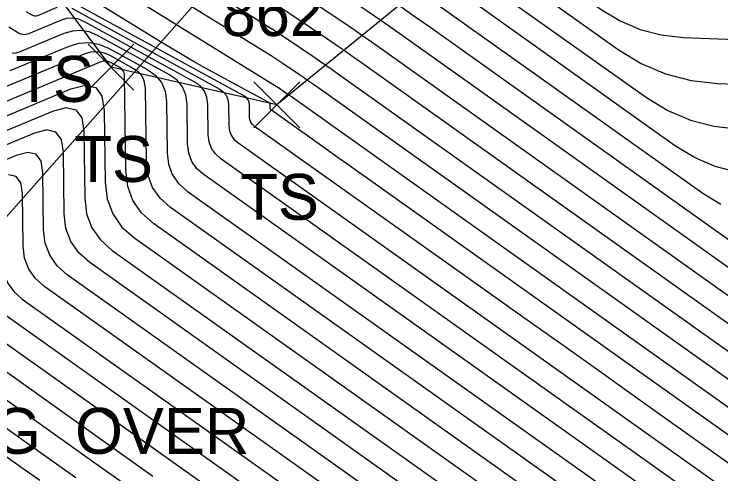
# Model space of a CAD drawing. Extents: x 1650836 to 1652450, y 332578 to 333908.
# Drawn here: x 1652155.83 to 1652186.58, y 332802.49 to 332822.5 of the extents above; entities that cross this region are included whole.
import ezdxf

# ---------------------------------------------------------------- set-up
doc = ezdxf.new("R2010")
doc.units = 0
for name, color, linetype in [('DCP', 7, 'Continuous'), ('L_A', 7, 'Continuous'), ('L_I', 7, 'Continuous'), ('L_TIC', 7, 'Continuous'), ('LELB', 7, 'Continuous'), ('LSOGCMA', 7, 'Continuous'), ('LSOGCMI', 7, 'Continuous'), ('M_C', 7, 'Continuous')]:
    doc.layers.add(name, color=color, linetype=linetype)

msp = doc.modelspace()

# ---------------------------------------------------------------- linework, layer by layer
at = {"layer": 'DCP'}
msp.add_lwpolyline([(1652097.436, 332748.039), (1652173.064, 332833.561)], dxfattribs=at)
at = {"layer": 'L_TIC'}
for points in [[(1652159.046, 332819.196), (1652161.046, 332821.196)], [(1652161.046, 332819.196), (1652159.046, 332821.196)], [(1652166.264, 332817.548), (1652168.264, 332819.548)], [(1652168.264, 332817.548), (1652166.264, 332819.548)]]:
    msp.add_lwpolyline(points, dxfattribs=at)
at = {"layer": 'LELB'}
msp.add_lwpolyline([(1652179.275, 332828.339), (1652167.264, 332818.548), (1652160.046, 332820.196), (1652157.477, 332823.68), (1652166.593, 332836.388)], dxfattribs=at)
at = {"layer": 'LSOGCMA'}
for points in [[(1652146.793, 332842.65), (1652157.507, 332833.342), (1652157.974, 332832.878), (1652158.365, 332832.365), (1652158.679, 332831.801), (1652158.916, 332831.187), (1652159.714, 332828.632), (1652159.96, 332828.029), (1652160.298, 332827.497), (1652160.728, 332827.037), (1652161.251, 332826.649), (1652166.303, 332823.515), (1652166.698, 332823.267), (1652167.091, 332823.015), (1652167.482, 332822.76), (1652167.869, 332822.501), (1652169.416, 332821.455), (1652169.802, 332821.193), (1652170.186, 332820.928), (1652170.569, 332820.661), (1652170.95, 332820.392), (1652190.692, 332806.342)], [(1652189.751, 332794.813), (1652162.63, 332814.09), (1652162.18, 332814.488), (1652161.856, 332814.952), (1652161.658, 332815.482), (1652161.587, 332816.079), (1652161.544, 332819.263), (1652161.509, 332819.54), (1652161.409, 332819.779), (1652161.245, 332819.979), (1652161.017, 332820.141), (1652159.977, 332820.71), (1652159.715, 332820.82), (1652159.45, 332820.866), (1652159.182, 332820.848), (1652158.91, 332820.766), (1652155.252, 332819.242)], [(1652161.871, 332802.38), (1652153.245, 332808.511), (1652152.988, 332808.739), (1652152.802, 332809.004), (1652152.689, 332809.307), (1652152.649, 332809.648), (1652152.629, 332811.087), (1652152.584, 332811.385), (1652152.456, 332811.558), (1652152.247, 332811.606), (1652151.956, 332811.53), (1652150.547, 332810.943), (1652150.205, 332810.841), (1652149.869, 332810.824), (1652149.539, 332810.891), (1652149.216, 332811.043), (1652146.021, 332812.978), (1652145.391, 332813.378), (1652144.847, 332813.757)]]:
    msp.add_lwpolyline(points, dxfattribs=at)
at = {"layer": 'LSOGCMI'}
for points in [[(1652160.714, 332847.161), (1652164.675, 332834.475), (1652164.777, 332834.225), (1652164.918, 332834.004), (1652165.096, 332833.813), (1652165.313, 332833.652), (1652166.257, 332833.066), (1652166.492, 332832.919), (1652166.726, 332832.769), (1652166.959, 332832.617), (1652167.19, 332832.463), (1652174.934, 332827.23), (1652175.747, 332826.677), (1652176.557, 332826.119), (1652177.363, 332825.556), (1652178.166, 332824.989), (1652181.371, 332822.708), (1652182.195, 332822.204), (1652183.064, 332821.833), (1652183.979, 332821.594), (1652184.939, 332821.488), (1652190.629, 332821.259)], [(1652186.578, 332814.214), (1652185.792, 332814.695), (1652174.966, 332822.4), (1652174.169, 332822.963), (1652173.37, 332823.521), (1652172.567, 332824.074), (1652171.761, 332824.623), (1652167.994, 332827.168), (1652167.452, 332827.53), (1652166.906, 332827.888), (1652166.356, 332828.24), (1652165.804, 332828.586), (1652163.586, 332829.962), (1652163.076, 332830.341), (1652162.657, 332830.789), (1652162.328, 332831.307), (1652162.088, 332831.895), (1652160.207, 332837.92), (1652159.756, 332839.084), (1652159.161, 332840.153), (1652158.42, 332841.128), (1652157.534, 332842.008), (1652153.435, 332845.569)], [(1652187.017, 332812.607), (1652173.962, 332821.898), (1652173.269, 332822.388), (1652172.574, 332822.873), (1652171.876, 332823.354), (1652171.175, 332823.831), (1652168.195, 332825.844), (1652167.575, 332826.259), (1652166.951, 332826.667), (1652166.322, 332827.07), (1652165.69, 332827.466), (1652163.154, 332829.039), (1652162.572, 332829.472), (1652162.092, 332829.985), (1652161.715, 332830.578), (1652161.441, 332831.25), (1652159.885, 332836.236), (1652159.487, 332837.263), (1652158.962, 332838.206), (1652158.308, 332839.066), (1652157.527, 332839.841), (1652151.774, 332844.84)], [(1652188.242, 332810.519), (1652172.958, 332821.396), (1652172.369, 332821.812), (1652171.778, 332822.225), (1652171.185, 332822.634), (1652170.588, 332823.039), (1652168.199, 332824.654), (1652167.6, 332825.054), (1652166.997, 332825.449), (1652166.39, 332825.838), (1652165.779, 332826.221), (1652162.722, 332828.117), (1652162.067, 332828.604), (1652161.527, 332829.181), (1652161.103, 332829.848), (1652160.795, 332830.605), (1652159.562, 332834.553), (1652159.218, 332835.442), (1652158.763, 332836.259), (1652158.197, 332837.003), (1652157.521, 332837.675), (1652150.114, 332844.11)], [(1652137.973, 332843.797), (1652157.487, 332826.843), (1652157.64, 332826.691), (1652157.768, 332826.523), (1652157.871, 332826.339), (1652157.948, 332826.138), (1652158.21, 332825.301), (1652158.29, 332825.104), (1652158.401, 332824.93), (1652158.542, 332824.779), (1652158.713, 332824.652), (1652167.089, 332819.457), (1652167.161, 332819.411), (1652167.233, 332819.365), (1652167.304, 332819.319), (1652167.375, 332819.271), (1652167.658, 332819.08), (1652167.729, 332819.032), (1652167.799, 332818.983), (1652167.869, 332818.935), (1652167.939, 332818.885), (1652194.367, 332800.077)], [(1652148.454, 332843.38), (1652157.514, 332835.509), (1652158.086, 332834.941), (1652158.564, 332834.312), (1652158.948, 332833.622), (1652159.239, 332832.87), (1652160.216, 332829.742), (1652160.516, 332829.004), (1652160.93, 332828.353), (1652161.457, 332827.79), (1652162.097, 332827.314), (1652166.041, 332824.868), (1652166.544, 332824.553), (1652167.044, 332824.232), (1652167.541, 332823.907), (1652168.034, 332823.577), (1652170.002, 332822.247), (1652170.493, 332821.913), (1652170.982, 332821.576), (1652171.469, 332821.237), (1652171.954, 332820.894), (1652189.467, 332808.43)], [(1652141.221, 332843.147), (1652157.494, 332829.01), (1652157.751, 332828.754), (1652157.967, 332828.47), (1652158.14, 332828.159), (1652158.271, 332827.821), (1652158.711, 332826.411), (1652158.847, 332826.079), (1652159.033, 332825.785), (1652159.27, 332825.532), (1652159.559, 332825.317), (1652166.827, 332820.809), (1652167.007, 332820.697), (1652167.186, 332820.582), (1652167.363, 332820.466), (1652167.54, 332820.348), (1652168.244, 332819.872), (1652168.42, 332819.752), (1652168.595, 332819.632), (1652168.769, 332819.51), (1652168.943, 332819.387), (1652193.142, 332802.166)], [(1652144.469, 332842.497), (1652157.5, 332831.176), (1652157.863, 332830.816), (1652158.166, 332830.417), (1652158.409, 332829.98), (1652158.594, 332829.504), (1652159.213, 332827.522), (1652159.403, 332827.054), (1652159.665, 332826.641), (1652159.999, 332826.284), (1652160.405, 332825.983), (1652166.565, 332822.162), (1652166.852, 332821.982), (1652167.138, 332821.799), (1652167.422, 332821.613), (1652167.705, 332821.424), (1652168.83, 332820.664), (1652169.111, 332820.473), (1652169.391, 332820.28), (1652169.669, 332820.086), (1652169.946, 332819.89), (1652191.917, 332804.254)], [(1652195.592, 332797.989), (1652171.198, 332815.35), (1652170.775, 332815.65), (1652170.352, 332815.951), (1652169.93, 332816.251), (1652169.507, 332816.552), (1652167.024, 332818.317), (1652167.001, 332818.337), (1652166.984, 332818.361), (1652166.974, 332818.389), (1652166.97, 332818.42), (1652166.968, 332818.551), (1652166.964, 332818.581), (1652166.953, 332818.607), (1652166.935, 332818.629), (1652166.91, 332818.647), (1652164.134, 332820.167), (1652163.664, 332820.429), (1652163.197, 332820.697), (1652162.734, 332820.971), (1652162.275, 332821.252), (1652157.867, 332823.986)], [(1652177.84, 332824.004), (1652182.117, 332820.96), (1652183.116, 332820.349), (1652184.17, 332819.899), (1652185.279, 332819.61), (1652186.443, 332819.481), (1652191.209, 332819.289)], [(1652196.817, 332795.901), (1652183.175, 332805.609), (1652181.466, 332806.825), (1652179.756, 332808.041), (1652178.047, 332809.257), (1652176.337, 332810.473), (1652166.292, 332817.612), (1652166.197, 332817.696), (1652166.129, 332817.793), (1652166.088, 332817.905), (1652166.073, 332818.03), (1652166.066, 332818.558), (1652166.05, 332818.682), (1652166.005, 332818.788), (1652165.932, 332818.877), (1652165.83, 332818.95), (1652157.779, 332823.359)], [(1652176.973, 332823.404), (1652183.342, 332818.872), (1652184.27, 332818.304), (1652185.25, 332817.886), (1652186.28, 332817.617), (1652187.361, 332817.498)], [(1652156.342, 332822.619), (1652156.595, 332822.466), (1652156.659, 332822.436), (1652156.725, 332822.423), (1652156.791, 332822.426), (1652156.859, 332822.446), (1652157.701, 332822.797)], [(1652158.338, 332822.764), (1652164.751, 332819.252), (1652164.929, 332819.125), (1652165.057, 332818.969), (1652165.135, 332818.783), (1652165.163, 332818.566), (1652165.176, 332817.64), (1652165.202, 332817.42), (1652165.275, 332817.225), (1652165.394, 332817.054), (1652165.559, 332816.908), (1652186.902, 332801.738)], [(1652187.28, 332815.625), (1652186.329, 332815.873), (1652185.424, 332816.259), (1652184.567, 332816.783), (1652175.969, 332822.902)], [(1652193.912, 332795.53), (1652164.827, 332816.204), (1652164.59, 332816.413), (1652164.42, 332816.657), (1652164.316, 332816.936), (1652164.278, 332817.249), (1652164.261, 332818.574), (1652164.221, 332818.883), (1652164.109, 332819.15), (1652163.926, 332819.373), (1652163.671, 332819.554), (1652158.896, 332822.169), (1652158.639, 332822.277), (1652158.378, 332822.323), (1652158.114, 332822.305), (1652157.847, 332822.224), (1652156.457, 332821.645), (1652156.345, 332821.612), (1652156.236, 332821.606), (1652156.128, 332821.628), (1652156.023, 332821.678), (1652155.605, 332821.931)], [(1652193.359, 332794.698), (1652164.095, 332815.499), (1652163.787, 332815.771), (1652163.565, 332816.089), (1652163.43, 332816.451), (1652163.381, 332816.859), (1652163.358, 332818.581), (1652163.306, 332818.984), (1652163.161, 332819.331), (1652162.923, 332819.621), (1652162.591, 332819.856), (1652159.455, 332821.574), (1652159.097, 332821.725), (1652158.733, 332821.788), (1652158.365, 332821.764), (1652157.992, 332821.651), (1652156.056, 332820.844), (1652155.9, 332820.798), (1652155.747, 332820.79)], [(1652155.654, 332820.043), (1652158.221, 332821.113), (1652158.657, 332821.244), (1652159.089, 332821.273), (1652159.515, 332821.199), (1652159.935, 332821.022), (1652161.606, 332820.107), (1652161.973, 332819.847), (1652162.236, 332819.525), (1652162.397, 332819.142), (1652162.454, 332818.697), (1652162.484, 332816.469), (1652162.544, 332815.967), (1652162.711, 332815.52), (1652162.983, 332815.13), (1652163.362, 332814.795), (1652192.807, 332793.866)], [(1652186.45, 332795.935), (1652161.897, 332813.386), (1652161.376, 332813.847), (1652161.001, 332814.384), (1652160.772, 332814.998), (1652160.69, 332815.689), (1652160.635, 332819.83), (1652160.62, 332819.939), (1652160.581, 332820.032), (1652160.517, 332820.111), (1652160.427, 332820.174), (1652160.019, 332820.398), (1652159.916, 332820.441), (1652159.812, 332820.46), (1652159.707, 332820.452), (1652159.6, 332820.42), (1652154.851, 332818.44)], [(1652154.449, 332817.639), (1652158.301, 332819.245), (1652158.929, 332819.409), (1652159.38, 332819.305), (1652159.654, 332818.933), (1652159.753, 332818.292), (1652159.794, 332815.192), (1652159.882, 332814.457), (1652160.125, 332813.804), (1652160.524, 332813.233), (1652161.078, 332812.743), (1652183.149, 332797.056)], [(1652154.047, 332816.838), (1652157.508, 332818.281), (1652158.093, 332818.434), (1652158.514, 332818.337), (1652158.77, 332817.989), (1652158.862, 332817.391), (1652158.901, 332814.499), (1652158.983, 332813.813), (1652159.21, 332813.204), (1652159.582, 332812.671), (1652160.099, 332812.214), (1652179.848, 332798.177)], [(1652176.547, 332799.299), (1652159.12, 332811.685), (1652158.64, 332812.11), (1652158.295, 332812.604), (1652158.084, 332813.17), (1652158.008, 332813.806), (1652157.972, 332816.491), (1652157.887, 332817.046), (1652157.649, 332817.368), (1652157.258, 332817.459), (1652156.715, 332817.316), (1652153.646, 332816.037)], [(1652173.246, 332800.42), (1652158.141, 332811.156), (1652157.698, 332811.548), (1652157.379, 332812.004), (1652157.185, 332812.526), (1652157.114, 332813.113), (1652157.081, 332815.59), (1652157.003, 332816.102), (1652156.783, 332816.4), (1652156.423, 332816.483), (1652155.922, 332816.352), (1652153.244, 332815.236)], [(1652146.751, 332816.078), (1652146.754, 332816.076), (1652147.232, 332815.711), (1652147.724, 332815.367), (1652148.232, 332815.044), (1652150.41, 332813.725), (1652150.873, 332813.508), (1652151.346, 332813.411), (1652151.827, 332813.436), (1652152.317, 332813.582), (1652154.335, 332814.423), (1652154.752, 332814.532), (1652155.052, 332814.463), (1652155.235, 332814.215), (1652155.301, 332813.789), (1652155.328, 332811.727), (1652155.387, 332811.238), (1652155.548, 332810.804), (1652155.814, 332810.424), (1652156.182, 332810.098), (1652168.54, 332801.315)], [(1652146.116, 332815.303), (1652146.414, 332815.075), (1652146.947, 332814.704), (1652147.495, 332814.355), (1652150.012, 332812.831), (1652150.429, 332812.635), (1652150.853, 332812.549), (1652151.286, 332812.571), (1652151.727, 332812.702), (1652153.542, 332813.459), (1652153.917, 332813.557), (1652154.187, 332813.495), (1652154.351, 332813.272), (1652154.41, 332812.888), (1652154.435, 332811.034), (1652154.488, 332810.595), (1652154.633, 332810.204), (1652154.872, 332809.862), (1652155.203, 332809.569), (1652166.317, 332801.67)], [(1652170.763, 332800.959), (1652157.161, 332810.627), (1652156.756, 332810.986), (1652156.464, 332811.404), (1652156.286, 332811.882), (1652156.221, 332812.42), (1652156.191, 332814.69), (1652156.119, 332815.159), (1652155.918, 332815.432), (1652155.588, 332815.508)], [(1652164.094, 332802.025), (1652154.224, 332809.04), (1652153.93, 332809.301), (1652153.718, 332809.604), (1652153.589, 332809.951), (1652153.542, 332810.341), (1652153.52, 332811.988), (1652153.468, 332812.328), (1652153.322, 332812.526), (1652153.082, 332812.582), (1652152.749, 332812.495), (1652151.137, 332811.823), (1652150.746, 332811.706), (1652150.361, 332811.686), (1652149.984, 332811.763), (1652149.614, 332811.937), (1652146.758, 332813.666), (1652146.169, 332814.041), (1652145.597, 332814.44), (1652145.48, 332814.529)], [(1652160.965, 332801.806), (1652159.648, 332802.735), (1652152.266, 332807.982), (1652152.046, 332808.177), (1652151.887, 332808.404), (1652151.79, 332808.663), (1652151.755, 332808.955), (1652151.739, 332810.187), (1652151.7, 332810.442), (1652151.591, 332810.59), (1652151.412, 332810.631), (1652151.162, 332810.566), (1652149.957, 332810.063), (1652149.664, 332809.976), (1652149.377, 332809.961), (1652149.094, 332810.019), (1652148.818, 332810.149), (1652145.283, 332812.289), (1652144.613, 332812.715), (1652144.218, 332812.991)], [(1652158.52, 332802.318), (1652157.424, 332803.091), (1652151.287, 332807.453), (1652151.104, 332807.615), (1652150.972, 332807.804), (1652150.891, 332808.02), (1652150.862, 332808.262), (1652150.849, 332809.286), (1652150.816, 332809.498), (1652150.725, 332809.621), (1652150.576, 332809.656), (1652150.369, 332809.601), (1652149.367, 332809.184), (1652149.123, 332809.111), (1652148.884, 332809.099), (1652148.65, 332809.147), (1652148.42, 332809.255), (1652144.546, 332811.6), (1652143.835, 332812.052), (1652143.589, 332812.224)], [(1652155.201, 332803.446), (1652156.074, 332802.83), (1652156.952, 332802.22)]]:
    msp.add_lwpolyline(points, dxfattribs=at)

# ---------------------------------------------------------------- texts
at = {"layer": 'L_A'}
for p in [(1652155.887, 332818.68), (1652158.455, 332815.196), (1652165.674, 332813.548)]:
    msp.add_text('TS', height=2, dxfattribs=at).set_placement(p)
at = {"layer": 'L_I'}
msp.add_text('862', height=2, dxfattribs=at).set_placement((1652164.855, 332821.548))
at = {"layer": 'M_C'}
msp.add_text('1.5 INCH DIA. LEANING  OVER', height=2, dxfattribs=at).set_placement((1652127.57, 332803.36))

doc.saveas('drawing.dxf')
